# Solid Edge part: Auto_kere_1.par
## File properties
Author: KULL
Template: Iso Metric Part.par
Last saved by: KULL
Revision: 48
Application: Solid Edge
Accuracy: 0,990
Face Style: Model Default
Fill Style: Normal
Coef. of Thermal Exp: 0.0
Thermal Conductivity: 0.0
Specific Heat: 0.0
Modulus of Elasticity: 0.0
Poisson's Ratio: 0.0
Yield Stress: 0.0
Ultimate Stress: 0.0
Elongation: 0.0
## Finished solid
Body 1: sheet body, 1 face, 4 edges, 4 vertices.
  Faces by surface: cylinder 1
  Edges by curve: circle 2, line 2
Body 2: sheet body, 1 face, 4 edges, 4 vertices.
  Faces by surface: cylinder 1
  Edges by curve: circle 2, line 2
Body 3: sheet body, 1 face, 4 edges, 4 vertices.
  Faces by surface: cylinder 1
  Edges by curve: circle 2, line 2
Body 4: sheet body, 1 face, 4 edges, 4 vertices.
  Faces by surface: cylinder 1
  Edges by curve: circle 2, line 2
Body 5: sheet body, 1 face, 4 edges, 4 vertices.
  Faces by surface: spline 1
  Edges by curve: curve on surface 3, spline 1
Body 6: sheet body, 1 face, 4 edges, 4 vertices.
  Faces by surface: cylinder 1
  Edges by curve: circle 2, line 2
Body 7: sheet body, 1 face, 4 edges, 4 vertices.
  Faces by surface: spline 1
  Edges by curve: curve on surface 4
Body 8: sheet body, 1 face, 4 edges, 4 vertices.
  Faces by surface: swept 1
  Edges by curve: line 2, spline 2
Body 9: sheet body, 1 face, 4 edges, 4 vertices.
  Faces by surface: swept 1
  Edges by curve: line 2, spline 2
Body 10: sheet body, 1 face, 4 edges, 4 vertices.
  Faces by surface: offset 1
  Edges by curve: curve on surface 4
Body 11: sheet body, 1 face, 4 edges, 4 vertices.
  Faces by surface: spline 1
  Edges by curve: curve on surface 3, circle 1
Body 12: sheet body, 1 face, 4 edges, 4 vertices.
  Faces by surface: spline 1
  Edges by curve: curve on surface 4
Body 13: sheet body, 1 face, 4 edges, 4 vertices.
  Faces by surface: offset 1
  Edges by curve: curve on surface 4
Body 14: sheet body, 1 face, 4 edges, 4 vertices.
  Faces by surface: spline 1
  Edges by curve: circle 2, spline 2
Body 15: sheet body, 1 face, 4 edges, 4 vertices.
  Faces by surface: spline 1
  Edges by curve: curve on surface 4
Body 16: solid body, 128 faces, 301 edges, 176 vertices.
  Faces by surface: blend 96, cylinder 12, plane 10, spline 6, offset 2, swept 2
  Edges by curve: intersection 184, circle 80, ellipse 24, line 13
Bounding box of the edges (mm; curved faces can reach further): 648.574 x 418.467 x 392.991, from (-507.184, -209.2334, -140.5972) to (141.3896, 209.2334, 252.3937).
Cylindrical faces by radius (mm): R54 x4, R62 x4, R516 x2, R540 x2, R598 x2, R600 x2, R2661.2303 x1
Planar faces by outward normal: +y 2, -y 2, -z 1, oblique 5
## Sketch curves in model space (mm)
line (-28.0915, 0, 21.6293) -> (-551.6652, 0, 42.7946)
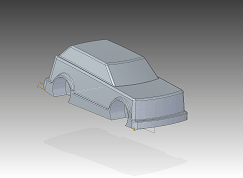
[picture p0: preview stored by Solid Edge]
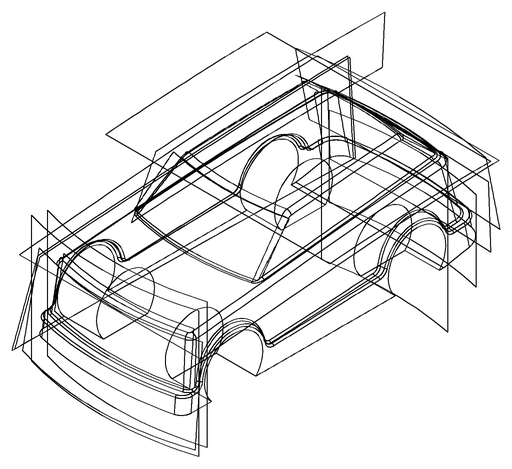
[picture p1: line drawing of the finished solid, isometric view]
